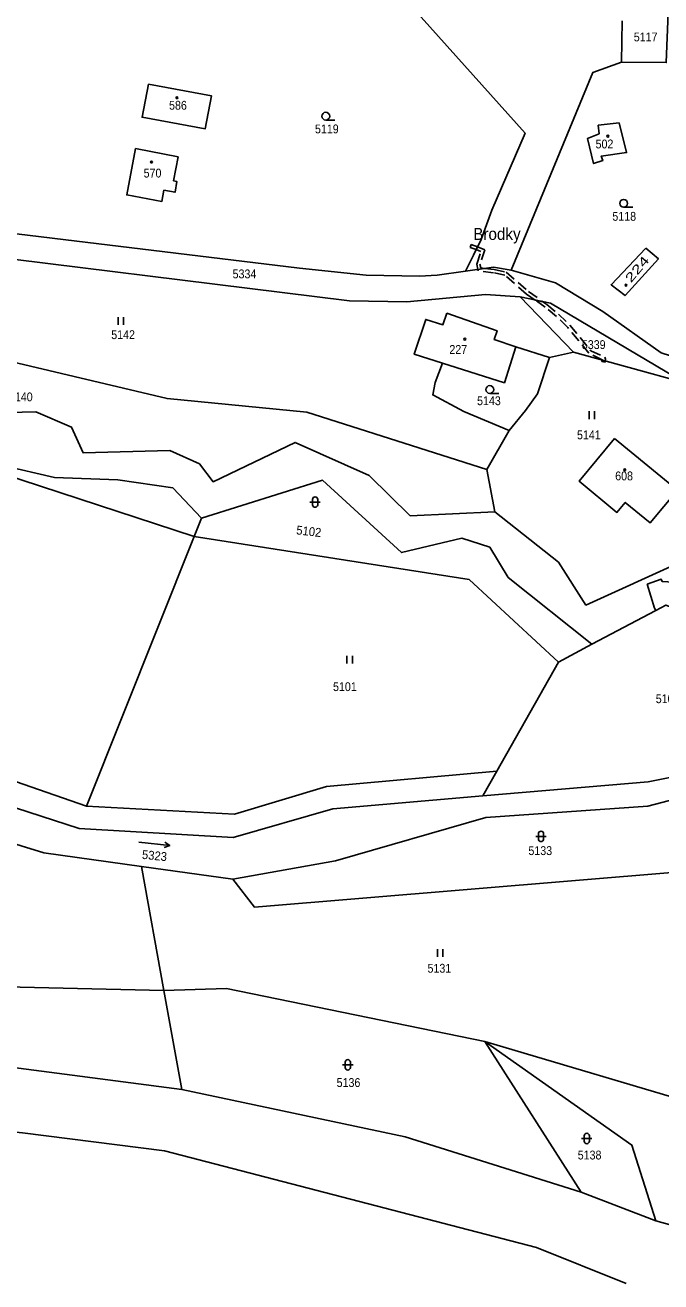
# Model space of a CAD drawing. Extents: x -665688 to -664583, y -1006118 to -1004927.
# Drawn here: x -664897.5 to -664775.4, y -1005645.6 to -1005404.2 of the extents above; entities that cross this region are included whole.
import ezdxf
from ezdxf.enums import TextEntityAlignment as Align

# ---------------------------------------------------------------- set-up
doc = ezdxf.new("R2010")
doc.units = 0
doc.header["$LTSCALE"] = 0.68
doc.linetypes.add('MEDIUM_DASHED', pattern=[4.5, 3, -1.5])
for name, color, linetype, lineweight in [('1', 7, 'Continuous', 25), ('25', 7, 'Continuous', 25), ('27', 7, 'MEDIUM_DASHED', 25)]:
    doc.layers.add(name, color=color, linetype=linetype, lineweight=lineweight)
for name, color, linetype in [('15', 7, 'Continuous'), ('18', 7, 'Continuous'), ('19', 7, 'Continuous')]:
    doc.layers.add(name, color=color, linetype=linetype)

msp = doc.modelspace()

# ---------------------------------------------------------------- linework, layer by layer
at = {"layer": '1'}
for p, q in [((-664863.59, -1005498.93), (-664865, -1005502.46)), ((-664865, -1005502.46), (-664885.68, -1005554.21)), ((-664776.37, -1005516.62), (-664788.63, -1005523.13))]:
    msp.add_line(p, q, dxfattribs=at)
for points in [[(-664812.89, -1005451.45), (-664811.38, -1005448.39), (-664809.91, -1005445.4), (-664807.84, -1005439.72), (-664801.49, -1005424.98), (-664834.73, -1005387.75), (-664840.95, -1005380.66), (-664847.73, -1005373.11)], [(-664774.02, -1005401.84), (-664774.38, -1005411.4), (-664782.97, -1005411.32), (-664782.81, -1005403.35)], [(-664804.12, -1005451.24), (-664788.5, -1005413.32), (-664782.97, -1005411.32)], [(-664812.89, -1005451.45), (-664818.34, -1005452.22), (-664821.75, -1005452.39), (-664832, -1005452.23), (-664844.79, -1005450.86), (-664916.08, -1005442.22), (-664952, -1005436.49)], [(-664958.68, -1005440.16), (-664918.99, -1005446.77), (-664835.18, -1005457.14), (-664824.19, -1005457.34), (-664809.08, -1005455.92), (-664802.4, -1005456.42), (-664792.15, -1005466.99), (-664796.78, -1005468.06), (-664803.23, -1005465.97)], [(-664969.3, -1005446.1), (-664945.43, -1005458.11), (-664870.22, -1005475.95), (-664843.38, -1005478.52), (-664808.84, -1005489.57), (-664807.3, -1005497.72)], [(-664804.12, -1005451.24), (-664807.51, -1005450.69), (-664812.89, -1005451.45)], [(-664765.04, -1005468.16), (-664768.77, -1005469.23), (-664775.33, -1005467.16), (-664786.56, -1005459.19), (-664795.61, -1005453.73), (-664804.12, -1005451.24)], [(-664807.3, -1005497.72), (-664823.52, -1005498.49), (-664831.43, -1005490.72), (-664845.63, -1005484.35), (-664861.39, -1005491.91), (-664864, -1005488.5), (-664869.71, -1005485.89), (-664886.34, -1005486.35), (-664888.54, -1005481.42), (-664895.39, -1005478.51), (-664911.15, -1005478.85), (-664917.14, -1005475.22), (-664920.29, -1005468.16), (-664939.44, -1005469.7), (-664948.5, -1005477.86), (-664952.19, -1005476.3), (-664954.45, -1005466.18), (-664962.99, -1005461.77), (-664976.12, -1005457.02), (-664981.8, -1005452.97)], [(-664865, -1005502.46), (-664927.78, -1005481.87), (-664956.61, -1005485.82), (-664964.51, -1005482.49), (-664972.73, -1005471.31), (-664988.54, -1005462.23), (-664995.99, -1005461.94), (-664985.67, -1005457.24)], [(-664985.67, -1005457.24), (-664975.78, -1005463.7), (-664959.79, -1005470.57), (-664964.6, -1005480.83), (-664955.25, -1005482.24), (-664940.12, -1005481), (-664936.96, -1005474.59), (-664924.8, -1005473.77), (-664915.63, -1005482.78), (-664902.52, -1005484.91), (-664901.73, -1005488.82), (-664891.82, -1005491.12), (-664879.66, -1005491.54), (-664869.11, -1005493.1), (-664863.59, -1005498.93)], [(-664802.4, -1005456.42), (-664796.61, -1005457.63), (-664770.82, -1005472.88), (-664792.15, -1005466.99)], [(-664816.48, -1005459.53), (-664817.24, -1005461.74), (-664820.54, -1005460.74), (-664822.77, -1005467.42), (-664817.35, -1005469.13)], [(-664803.23, -1005465.97), (-664807.4, -1005464.59), (-664806.84, -1005462.92), (-664816.48, -1005459.53)], [(-664817.35, -1005469.13), (-664805.43, -1005472.89), (-664803.23, -1005465.97)], [(-664817.35, -1005469.13), (-664818.77, -1005472.85), (-664819.2, -1005475.22), (-664813.26, -1005478.44), (-664804.54, -1005482.04), (-664808.84, -1005489.57)], [(-664796.78, -1005468.06), (-664799.11, -1005475.05), (-664801.38, -1005478.24), (-664804.54, -1005482.04)], [(-665116, -1005486.34), (-665037.17, -1005561.39), (-665010.92, -1005583.28), (-664991.78, -1005592.85), (-664962.41, -1005603.78), (-664921.71, -1005614.59), (-664897.94, -1005616.96), (-664870.69, -1005620.43), (-664799.26, -1005639.02), (-664782.09, -1005645.9)], [(-664863.59, -1005498.93), (-664840.37, -1005491.62), (-664825.2, -1005505.51), (-664813.63, -1005502.78), (-664808.25, -1005504.49), (-664804.72, -1005510.29), (-664788.63, -1005523.13)], [(-664762.11, -1005504.56), (-664771.39, -1005507.22), (-664789.8, -1005515.61), (-664795.07, -1005507.35), (-664807.3, -1005497.72)], [(-664865, -1005502.46), (-664812.23, -1005510.71), (-664795.07, -1005526.57)], [(-664809.58, -1005552.27), (-664838.4, -1005554.75), (-664857.53, -1005560.23), (-664887.07, -1005558.49), (-664933.48, -1005543.45), (-664952.44, -1005532.63), (-664991.45, -1005525.08), (-665012.03, -1005508)], [(-664990.99, -1005508.78), (-664989.85, -1005519.48), (-664950.5, -1005527.4), (-664931.25, -1005538.39), (-664885.68, -1005554.21)], [(-664746.83, -1005530.12), (-664755.79, -1005541.41), (-664769.9, -1005547.96), (-664777.87, -1005549.55), (-664809.58, -1005552.27), (-664806.9, -1005547.53), (-664795.07, -1005526.57), (-664788.63, -1005523.13)], [(-664875.12, -1005565.84), (-664893.9, -1005563.22), (-664947.17, -1005546.75), (-665000.93, -1005525.33)], [(-664857.56, -1005568.28), (-664837.85, -1005564.71), (-664809.01, -1005556.42), (-664777.88, -1005554.25), (-664768.66, -1005551.79), (-664753.33, -1005544.68), (-664742.26, -1005533.2)], [(-664741.2, -1005543.33), (-664760.39, -1005554.64), (-664771.75, -1005566.81), (-664853.43, -1005573.61), (-664857.56, -1005568.28)], [(-664885.68, -1005554.21), (-664857.27, -1005555.74), (-664839.63, -1005550.42), (-664806.9, -1005547.53)], [(-664867.38, -1005608.64), (-664916.88, -1005602.2), (-664931.13, -1005599.43), (-664964.98, -1005588.84), (-664964.12, -1005586.74), (-664954.79, -1005564.05)], [(-664954.79, -1005564.05), (-664941.98, -1005576.5), (-664912.3, -1005588.7), (-664870.82, -1005589.64), (-664867.38, -1005608.64)], [(-664809.2, -1005599.44), (-664858.81, -1005589.22), (-664870.82, -1005589.64), (-664875.12, -1005565.84), (-664857.56, -1005568.28)], [(-664809.2, -1005599.44), (-664765.6, -1005612.38), (-664755.06, -1005639.78), (-664776.38, -1005633.86)], [(-664790.7, -1005628.4), (-664824.48, -1005617.72), (-664867.38, -1005608.64)]]:
    msp.add_lwpolyline(points, dxfattribs=at)
for points in [[(-664873.8, -1005415.56), (-664861.71, -1005417.77), (-664862.88, -1005424.11), (-664875.01, -1005421.9)], [(-664783.42, -1005422.94), (-664787.43, -1005423.42), (-664787.28, -1005425.07), (-664789.51, -1005426), (-664788.31, -1005430.81), (-664786.57, -1005430.23), (-664786.85, -1005429.35), (-664782, -1005428.69)], [(-664876.25, -1005427.9), (-664868.1, -1005429.53), (-664868.96, -1005434.1), (-664868.35, -1005434.21), (-664868.68, -1005436.29), (-664870.83, -1005435.91), (-664871.21, -1005438.06), (-664877.94, -1005436.83)], [(-664778.31, -1005447.03), (-664784.97, -1005454.08), (-664782.28, -1005456.14), (-664775.89, -1005449.12)], [(-664784.31, -1005483.59), (-664791.1, -1005491.79), (-664783.83, -1005497.81), (-664782.23, -1005495.87), (-664777.47, -1005499.81), (-664772.24, -1005493.54)], [(-664778.03, -1005511.58), (-664776.64, -1005516.17), (-664776.37, -1005516.62), (-664774.44, -1005515.6), (-664765.82, -1005518.88), (-664764.8, -1005516.35), (-664763.65, -1005515.05), (-664758.83, -1005517.16), (-664758.59, -1005516.71), (-664769.79, -1005511.58), (-664770.15, -1005511.46), (-664771.06, -1005510.81), (-664771.29, -1005510.91), (-664771.4, -1005510.73), (-664771.84, -1005511.25), (-664775.14, -1005511.1), (-664775.37, -1005510.61)], [(-664809.2, -1005599.44), (-664780.95, -1005619.34), (-664776.38, -1005633.86), (-664790.7, -1005628.4)]]:
    msp.add_lwpolyline(points, close=True, dxfattribs=at)
at = {"layer": '25'}
for p, q in [((-664839.74, -1005422.45), (-664837.99, -1005422.45)), ((-664782.55, -1005439.19), (-664780.8, -1005439.19)), ((-664879.597, -1005461.795), (-664879.597, -1005460.295)), ((-664878.563, -1005461.795), (-664878.563, -1005460.295)), ((-664808.25, -1005474.95), (-664806.5, -1005474.95)), ((-664789.197, -1005479.865), (-664789.197, -1005478.365)), ((-664788.163, -1005479.865), (-664788.163, -1005478.365)), ((-664842.79, -1005495.82), (-664840.79, -1005495.82)), ((-664842.29, -1005496.32), (-664842.29, -1005495.32)), ((-664841.29, -1005495.32), (-664841.29, -1005496.32)), ((-664835.667, -1005526.845), (-664835.667, -1005525.345)), ((-664834.633, -1005526.845), (-664834.633, -1005525.345)), ((-664875.653, -1005561.132), (-664869.687, -1005561.768)), ((-664799.41, -1005560.03), (-664797.41, -1005560.03)), ((-664798.91, -1005560.53), (-664798.91, -1005559.53)), ((-664797.91, -1005559.53), (-664797.91, -1005560.53)), ((-664818.317, -1005583.165), (-664818.317, -1005581.665)), ((-664817.283, -1005583.165), (-664817.283, -1005581.665)), ((-664836.51, -1005603.91), (-664834.51, -1005603.91)), ((-664836.01, -1005604.41), (-664836.01, -1005603.41)), ((-664835.01, -1005603.41), (-664835.01, -1005604.41)), ((-664790.63, -1005618.06), (-664788.63, -1005618.06)), ((-664790.13, -1005618.56), (-664790.13, -1005617.56)), ((-664789.13, -1005617.56), (-664789.13, -1005618.56))]:
    msp.add_line(p, q, dxfattribs=at)
msp.add_lwpolyline([(-664870.629, -1005561.166), (-664869.687, -1005561.768), (-664870.735, -1005562.159)], dxfattribs=at)
for centre, radius in [((-664868.32, -1005418.14), 0.175), ((-664839.74, -1005421.7), 0.75), ((-664785.58, -1005425.52), 0.175), ((-664873.2, -1005430.5), 0.175), ((-664782.55, -1005438.44), 0.75), ((-664782.1, -1005454.16), 0.175), ((-664813.05, -1005464.52), 0.175), ((-664808.25, -1005474.2), 0.75), ((-664782.34, -1005489.62), 0.174)]:
    msp.add_circle(centre, radius, dxfattribs=at)
for centre, start, end in [((-664841.79, -1005495.32), 0.101, 180.00143), ((-664841.79, -1005496.32), 180.10243, 0.00286), ((-664798.41, -1005559.53), 0.101, 180.00143), ((-664798.41, -1005560.53), 180.10243, 0.00286), ((-664835.51, -1005603.41), 0.101, 180.00143), ((-664835.51, -1005604.41), 180.10243, 0.00286), ((-664789.63, -1005617.56), 0.101, 180.00143), ((-664789.63, -1005618.56), 180.10243, 0.00286)]:
    msp.add_arc(centre, 0.5, start, end, dxfattribs=at)
at = {"layer": '27'}
for p, q in [((-664810.86, -1005447.33), (-664810.59, -1005446.79)), ((-664810.54, -1005451.12), (-664809.25, -1005450.94)), ((-664809.25, -1005450.94), (-664810.54, -1005451.12)), ((-664799.52, -1005457.02), (-664798.05, -1005457.33)), ((-664798.05, -1005457.33), (-664799.52, -1005457.02))]:
    msp.add_line(p, q, dxfattribs=at)
msp.add_lwpolyline([(-664812.04, -1005446.93), (-664811.85, -1005446.36), (-664810.59, -1005446.79), (-664810.86, -1005447.33)], close=True, dxfattribs=at)
for points in [[(-664810.54, -1005451.12), (-664810.76, -1005450.09), (-664809.96, -1005447.68), (-664810.86, -1005447.33)], [(-664810.59, -1005446.79), (-664809.22, -1005447.34), (-664810.14, -1005450.13), (-664809.99, -1005450.84), (-664809.25, -1005450.94)], [(-664799.52, -1005457.02), (-664801.19, -1005455.85), (-664805.36, -1005452.2), (-664807.51, -1005451.77), (-664810.49, -1005451.38), (-664810.54, -1005451.12)], [(-664809.25, -1005450.94), (-664807.41, -1005451.17), (-664805.08, -1005451.64), (-664800.81, -1005455.37), (-664798.05, -1005457.33)], [(-664786.65, -1005468.51), (-664789.25, -1005467.22), (-664793.3, -1005462.26), (-664795.47, -1005460.15), (-664797.63, -1005458.36), (-664799.52, -1005457.02)], [(-664798.05, -1005457.33), (-664797.27, -1005457.88), (-664795.07, -1005459.71), (-664792.86, -1005461.86), (-664788.87, -1005466.74), (-664786.17, -1005468), (-664786.01, -1005468.39), (-664786.07, -1005468.67), (-664786.13, -1005468.96), (-664786.72, -1005468.83), (-664786.65, -1005468.51)]]:
    msp.add_lwpolyline(points, dxfattribs=at)

# ---------------------------------------------------------------- texts
at = {"layer": '15', "width": 0.95}
msp.add_text('Brodky', height=2.3, dxfattribs=at).set_placement((-664806.8795, -1005445.46), align=Align.CENTER)
at = {"layer": '18', "width": 0.9}
for s, p in [('5117', (-664778.3295, -1005407.32)), ('5119', (-664839.5395, -1005424.99)), ('5118', (-664782.4395, -1005441.78)), ('5334', (-664855.3495, -1005452.84)), ('5142', (-664878.6495, -1005464.51)), ('5339', (-664788.2995, -1005466.42)), ('5140', (-664898.2895, -1005476.46)), ('5143', (-664808.4195, -1005477.2)), ('5141', (-664789.2295, -1005483.75)), ('5101', (-664836.0695, -1005532.12)), ('5103', (-664774.1095, -1005534.44)), ('5133', (-664798.5595, -1005563.62)), ('5131', (-664817.9295, -1005586.22)), ('5136', (-664835.3795, -1005608.17)), ('5138', (-664789.0895, -1005622.09))]:
    msp.add_text(s, height=1.7, dxfattribs=at).set_placement(p, align=Align.CENTER)
at = {"layer": '18', "width": 0.95}
for s, rotation, p in [('5102', 353.603, (-664843.0872, -1005502.2742)), ('5323', 354.403, (-664872.7044, -1005564.5686))]:
    msp.add_text(s, height=1.7, rotation=rotation, dxfattribs=at).set_placement(p, align=Align.CENTER)
at = {"layer": '19', "width": 0.9}
for s, p in [('586', (-664868.1195, -1005420.45)), ('570', (-664872.9995, -1005433.47)), ('608', (-664782.4695, -1005491.64))]:
    msp.add_text(s, height=1.7, dxfattribs=at).set_placement(p, align=Align.CENTER)
for s, p in [('502', (-664787.94, -1005427.88)), ('227', (-664816.01, -1005467.35))]:
    msp.add_text(s, height=1.7, dxfattribs=at).set_placement(p)
at = {"layer": '19', "width": 1.5}
msp.add_text('224', height=1.7, rotation=50, dxfattribs=at).set_placement((-664781.144, -1005453.799))

doc.saveas('drawing.dxf')
